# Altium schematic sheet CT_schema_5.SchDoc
size 293 x 258 mm
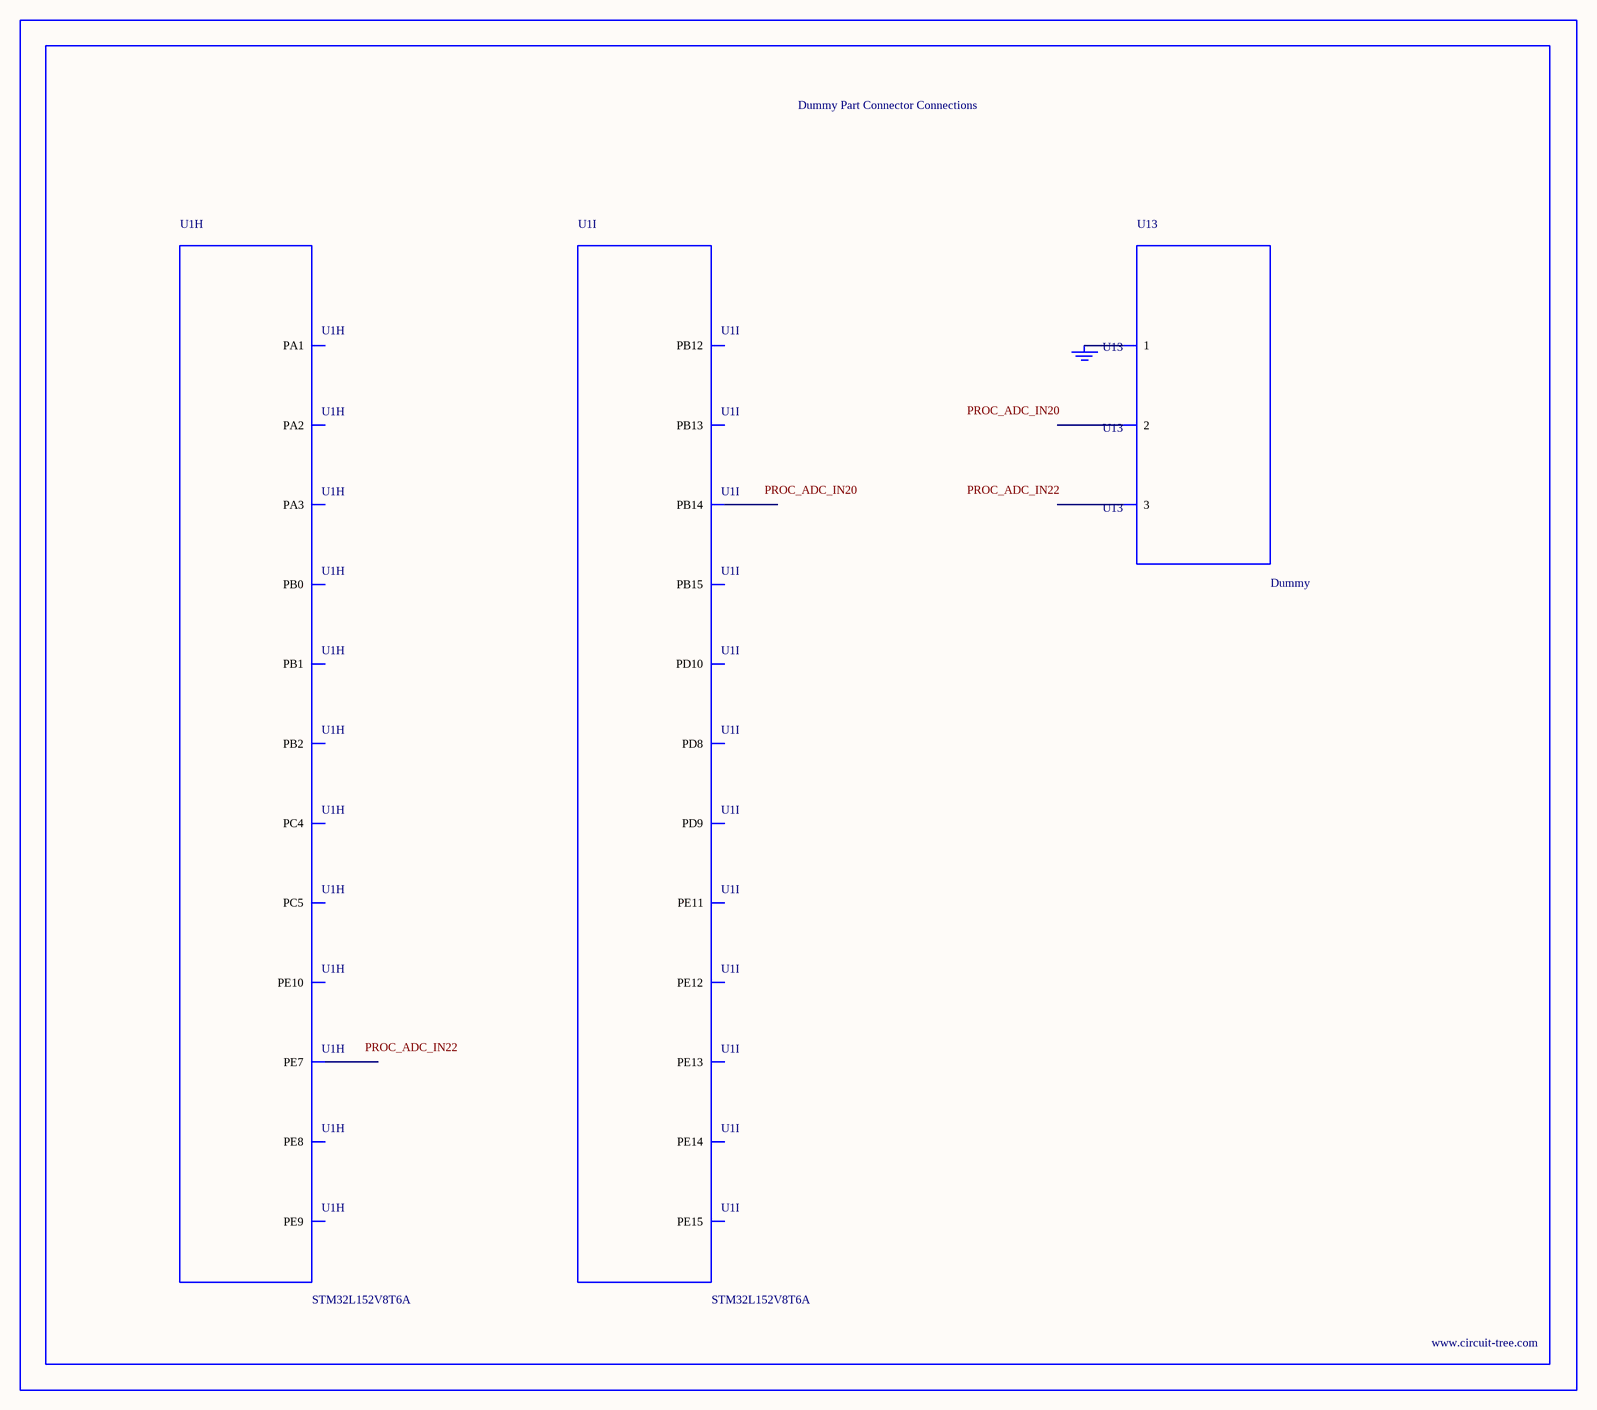
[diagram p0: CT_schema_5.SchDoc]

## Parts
BORDER4  (no value)
GND_INSTANCE_4_0  (no value)
U1  STM32L152V8T6A  [LQFP100]  (parts H,I of 9)
U13  Dummy  [DUMMY_PACKAGE_133]

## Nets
NetGND_INSTANCE_4_0_0: GND_INSTANCE_4_0.0(GND) U13.1

Not connected (* = marked no-connect by the designer): U1 24(PA1) 25(PA2) 26(PA3) 33(PC4) 34(PC5) 35(PB0) 36(PB1) 37(PB2) 38(PE7) 39(PE8) 40(PE9) 41(PE10) 42(PE11) 43(PE12) 44(PE13) 45(PE14) 46(PE15) 51(PB12) 52(PB13) 53(PB14) 54(PB15) 55(PD8) 56(PD9) 57(PD10); U13 2 3

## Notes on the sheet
- Labels drawn without touching a wire or pin: PROC_ADC_IN20, PROC_ADC_IN22

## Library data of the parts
BORDER4 = BORDER_PAGE4
GND_INSTANCE_4_0 = GND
